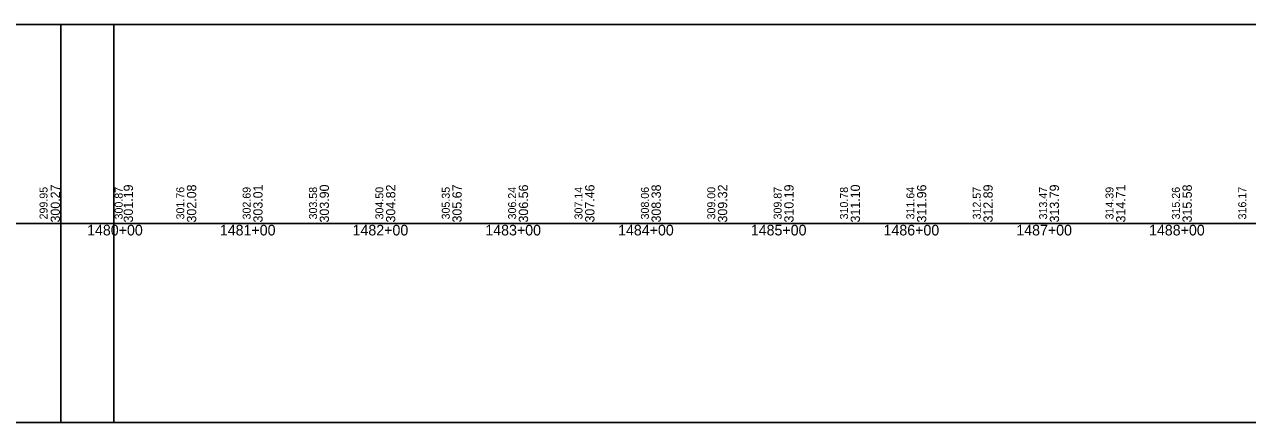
# Model space of a CAD drawing. Extents: x -3627 to 47473, y 2850 to 4350.
# Drawn here: x 35406 to 36327, y 2850 to 3150 of the extents above; entities that cross this region are included whole.
import ezdxf

# ---------------------------------------------------------------- set-up
doc = ezdxf.new("R2010")
doc.units = 0
for name, color, linetype in [('RD_DDB_StaTX', 7, 'Continuous'), ('RD_DDB_StripGrade', 7, 'Continuous'), ('RD_GPK_Profile_Cell', 7, 'Continuous'), ('RD_SHT_ShtClip', 7, 'Continuous')]:
    doc.layers.add(name, color=color, linetype=linetype)

msp = doc.modelspace()

# ---------------------------------------------------------------- linework, layer by layer
at = {"layer": 'RD_GPK_Profile_Cell'}
msp.add_line((1000, 3000), (46705.077602, 3000), dxfattribs=at)
at = {"layer": 'RD_SHT_ShtClip'}
for points in [[(33933.33, 3150), (35473.33, 3150), (35473.33, 2850), (33933.33, 2850)], [(35433.33, 3150), (36973.33, 3150), (36973.33, 2850), (35433.33, 2850)]]:
    msp.add_lwpolyline(points, close=True, dxfattribs=at)

# ---------------------------------------------------------------- texts
at = {"layer": 'RD_DDB_StaTX'}
for s, p in [('1480+00', (35453.125471, 2991)), ('1481+00', (35553.125471, 2991)), ('1482+00', (35653.125471, 2991)), ('1483+00', (35753.125471, 2991)), ('1484+00', (35853.125471, 2991)), ('1485+00', (35953.125471, 2991)), ('1486+00', (36053.125471, 2991)), ('1487+00', (36153.125471, 2991)), ('1488+00', (36253.125471, 2991))]:
    msp.add_text(s, height=8, dxfattribs=at).set_placement(p)
at = {"layer": 'RD_DDB_StripGrade'}
for s, height, p in [('299.95', 6, (35423.33, 3003.073688)), ('300.27', 7, (35432.682987, 3000.75)), ('300.87', 6, (35479.917743, 3003.073688)), ('301.19', 7, (35487.665565, 3000.75)), ('301.76', 6, (35526.33, 3003.073688)), ('302.08', 7, (35535.33, 3000.75)), ('302.69', 6, (35576.33, 3003.073688)), ('303.01', 7, (35585.33, 3000.75)), ('303.58', 6, (35626.33, 3003.073688)), ('303.90', 7, (35635.33, 3000.75)), ('304.50', 6, (35676.33, 3003.073688)), ('304.82', 7, (35685.33, 3000.75)), ('305.35', 6, (35726.33, 3003.073688)), ('305.67', 7, (35735.33, 3000.75)), ('306.24', 6, (35776.33, 3003.073688)), ('306.56', 7, (35785.33, 3000.75)), ('307.14', 6, (35826.33, 3003.073688)), ('307.46', 7, (35835.33, 3000.75)), ('308.06', 6, (35876.33, 3003.073688)), ('308.38', 7, (35885.33, 3000.75)), ('309.00', 6, (35926.33, 3003.073688)), ('309.32', 7, (35935.33, 3000.75)), ('309.87', 6, (35976.33, 3003.073688)), ('310.19', 7, (35985.33, 3000.75)), ('310.78', 6, (36026.33, 3003.073688)), ('311.10', 7, (36035.33, 3000.75)), ('311.64', 6, (36076.33, 3003.073688)), ('311.96', 7, (36085.33, 3000.75)), ('312.57', 6, (36126.33, 3003.073688)), ('312.89', 7, (36135.33, 3000.75)), ('313.47', 6, (36176.33, 3003.073688)), ('313.79', 7, (36185.33, 3000.75)), ('314.39', 6, (36226.33, 3003.073688)), ('314.71', 7, (36235.33, 3000.75)), ('315.26', 6, (36276.33, 3003.073688)), ('315.58', 7, (36285.33, 3000.75)), ('316.17', 6, (36326.33, 3003.073688))]:
    msp.add_text(s, height=height, rotation=90, dxfattribs=at).set_placement(p)

doc.saveas('drawing.dxf')
